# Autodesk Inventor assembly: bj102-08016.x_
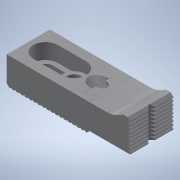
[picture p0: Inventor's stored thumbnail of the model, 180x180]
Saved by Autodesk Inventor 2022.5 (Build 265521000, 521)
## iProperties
Part Number: bj102-08016.x_
Material: 一般
Document SubType Name: Assembly
Designer: ImaoCorp
Sending System: SOLIDWORKS 2017-2017317
MC: AMD64
MC_MODEL: Intel64 Family 6 Model 60 Stepping 3, GenuineIntel
OS: Windows_NT
FRU: Parasolid Version 29.0, build 201,  4-17-2017
FORMAT: text
GUISE: transmit
KEY: bj102-08016
FILE: bj102-08016.x_t
DATE: Fri Mar 15 10:32:41 2019
Author: ImaoCorp
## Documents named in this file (4)
- X:\14_SW2022-Inv2022\00_全2023-1023新製品(TCC)まで\b\bj102-08016\BJ102-08016.iam
- X:\14_SW2022-Inv2022\00_全2023-1023新製品(TCC)まで\b\bj102-08016\bj102-08016_01.ipt
- X:\14_SW2022-Inv2022\00_全2023-1023新製品(TCC)まで\b\bj102-08016\bj102-08016_02.ipt
- X:\14_SW2022-Inv2022\00_全2023-1023新製品(TCC)まで\b\bj102-08016\bj102-08016_03.ipt
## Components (3 placed, 3 different names)
1. bj102-08016_01
2. bj102-08016_02
3. bj102-08016_03
